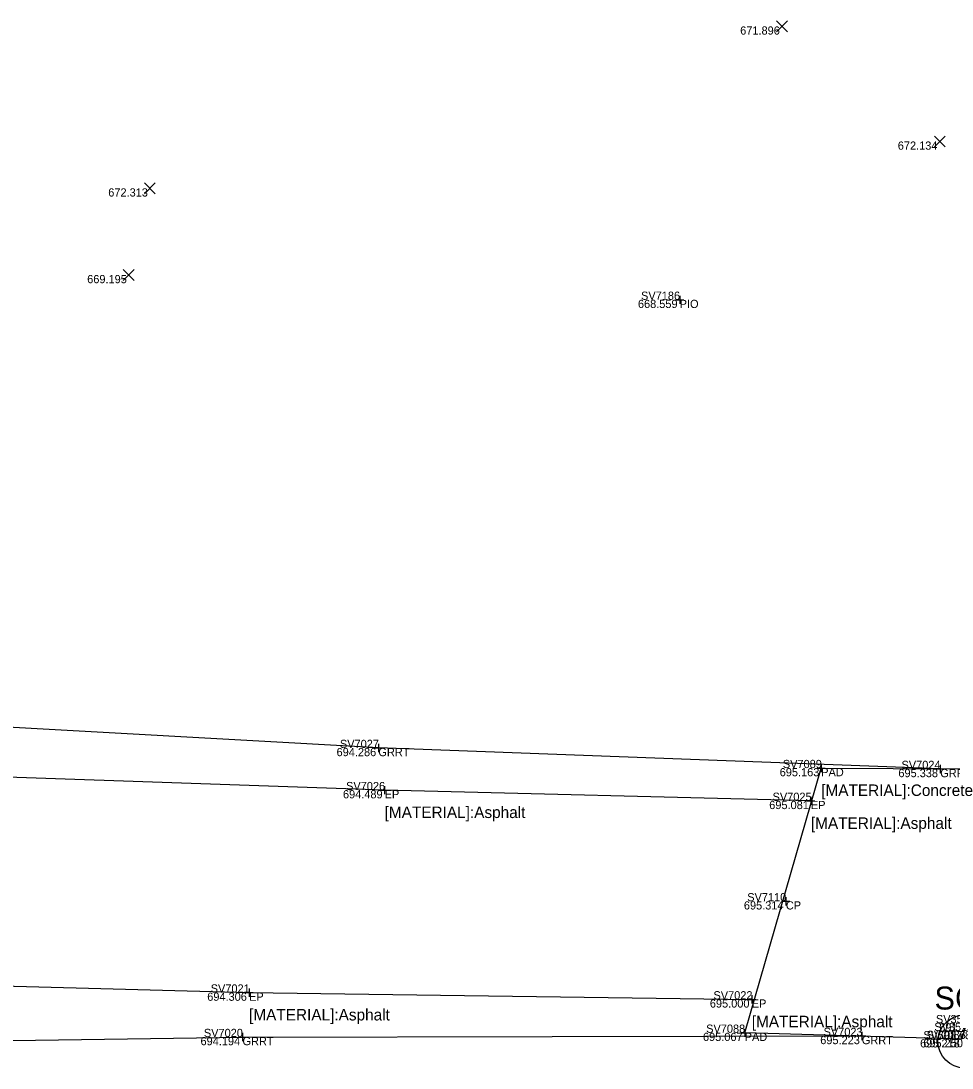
# Model space of a CAD drawing. Extents: x 1660019 to 1662995, y 619975 to 620342.
# Drawn here: x 1661112.6 to 1661226.1, y 620214.3 to 620342 of the extents above; entities that cross this region are included whole.
import ezdxf

# ---------------------------------------------------------------- set-up
doc = ezdxf.new("R2010")
doc.units = 0
for name, color, linetype in [('BR_X_Rail_Object', 7, 'Continuous'), ('BR_X_SV_Bottom_of_Beam_Text', 7, 'Continuous'), ('BR_X_SV_Deck_Top_Text', 7, 'Continuous'), ('DR_X_Elev_Flow', 7, 'Continuous'), ('PV_X_EOP', 7, 'Continuous'), ('RD_P_GR_Lt', 7, 'Continuous'), ('RD_P_GR_Rt', 7, 'Continuous'), ('RD_X_Concrete_Pad', 7, 'Continuous'), ('RD_X_GR_Bar', 7, 'Continuous'), ('RD_X_GR_Rt', 7, 'Continuous'), ('RD_X_Text', 7, 'Continuous'), ('RD_X_Wall', 7, 'Continuous'), ('SC_Scratch6', 7, 'Continuous'), ('SV_X_Text', 7, 'Continuous')]:
    doc.layers.add(name, color=color, linetype=linetype)

msp = doc.modelspace()

# ---------------------------------------------------------------- linework, layer by layer
at = {"layer": 'DR_X_Elev_Flow'}
for p, q in [((1661192.42, 620307.99), (1661193.42, 620307.99)), ((1661192.92, 620308.49), (1661192.92, 620307.49)), ((1661192.92, 620307.99), (1661192.92, 620307.99))]:
    msp.add_line(p, q, dxfattribs=at)
at = {"layer": 'PV_X_EOP'}
for points in [[(1661208.92, 620246.9), (1661156.94, 620248.21), (1661087.29, 620250.6), (1661037.39, 620250.48), (1660981.01, 620252.16), (1660916.41, 620253.34), (1660855.2, 620254.44), (1660801.44, 620255.57), (1660749.64, 620256.49), (1660700.03, 620257.78), (1660643.44, 620258.64), (1660593.17, 620259.57)], [(1660597.37, 620234.1), (1660651.64, 620233.44), (1660703.42, 620232.61), (1660757.32, 620231.35), (1660809.76, 620230.12), (1660857.03, 620229.26), (1660910.07, 620228.44), (1660968.25, 620227.38), (1661028.27, 620226.15), (1661081.58, 620225.11), (1661140.41, 620223.53), (1661201.71, 620222.7)]]:
    msp.add_lwpolyline(points, dxfattribs=at)
at = {"layer": 'RD_P_GR_Lt'}
for p, q in [((1661155.68, 620253.35), (1661156.68, 620253.35)), ((1661156.18, 620253.85), (1661156.18, 620252.85)), ((1661156.18, 620253.35), (1661156.18, 620253.35)), ((1661209.68, 620250.9), (1661210.68, 620250.9)), ((1661210.18, 620251.4), (1661210.18, 620250.4)), ((1661210.18, 620250.9), (1661210.18, 620250.9)), ((1661224.19, 620250.79), (1661225.19, 620250.79)), ((1661224.69, 620251.29), (1661224.69, 620250.29)), ((1661224.69, 620250.79), (1661224.69, 620250.79)), ((1661156.44, 620248.21), (1661157.44, 620248.21)), ((1661156.94, 620248.71), (1661156.94, 620247.71)), ((1661156.94, 620248.21), (1661156.94, 620248.21)), ((1661208.42, 620246.9), (1661209.42, 620246.9)), ((1661208.92, 620247.4), (1661208.92, 620246.4)), ((1661208.92, 620246.9), (1661208.92, 620246.9)), ((1661205.87, 620235.16), (1661205.87, 620234.16)), ((1661205.37, 620234.66), (1661206.37, 620234.66)), ((1661205.87, 620234.66), (1661205.87, 620234.66)), ((1661140.41, 620224.03), (1661140.41, 620223.03)), ((1661139.91, 620223.53), (1661140.91, 620223.53)), ((1661140.41, 620223.53), (1661140.41, 620223.53)), ((1661201.21, 620222.7), (1661202.21, 620222.7)), ((1661201.71, 620223.2), (1661201.71, 620222.2)), ((1661201.71, 620222.7), (1661201.71, 620222.7)), ((1661139.61, 620218.61), (1661139.61, 620217.61)), ((1661200.35, 620218.63), (1661201.35, 620218.63)), ((1661200.85, 620219.13), (1661200.85, 620218.13)), ((1661200.85, 620218.63), (1661200.85, 620218.63)), ((1661215.13, 620218.74), (1661215.13, 620217.74)), ((1661139.11, 620218.11), (1661140.11, 620218.11)), ((1661139.61, 620218.11), (1661139.61, 620218.11)), ((1661214.63, 620218.24), (1661215.63, 620218.24)), ((1661215.13, 620218.24), (1661215.13, 620218.24))]:
    msp.add_line(p, q, dxfattribs=at)
at = {"layer": 'RD_P_GR_Rt'}
for p, q in [((1661204.73, 620340.65), (1661206.07, 620341.99)), ((1661204.73, 620341.99), (1661206.07, 620340.65)), ((1661223.98, 620326.62), (1661225.31, 620327.95)), ((1661223.98, 620327.95), (1661225.31, 620326.62)), ((1661127.64, 620320.91), (1661128.97, 620322.25)), ((1661127.64, 620322.25), (1661128.97, 620320.91)), ((1661125.07, 620310.34), (1661126.4, 620311.68)), ((1661125.07, 620311.68), (1661126.4, 620310.34))]:
    msp.add_line(p, q, dxfattribs=at)
at = {"layer": 'RD_X_Concrete_Pad'}
msp.add_lwpolyline([(1661227.34, 620217.84), (1661200.85, 620218.63), (1661210.18, 620250.9), (1661236.48, 620250.77)], close=True, dxfattribs=at)
at = {"layer": 'RD_X_GR_Rt'}
for points in [[(1661224.69, 620250.79), (1661156.18, 620253.35), (1661087.54, 620257.19), (1661037.26, 620258.5), (1660981.37, 620259.47), (1660918.68, 620260.81), (1660856.77, 620262.08), (1660800.7, 620262.74), (1660750.31, 620264.54), (1660700.27, 620265.16), (1660644.43, 620266.52), (1660592.86, 620267.53)], [(1660596.86, 620226.32), (1660650.68, 620225.81), (1660702.7, 620224.83), (1660759.05, 620223.97), (1660808.86, 620222.78), (1660856.77, 620221.69), (1660908.98, 620220.55), (1660971.26, 620219.59), (1661027.54, 620217.92), (1661083.51, 620217.29), (1661139.61, 620218.11), (1661215.13, 620218.24)]]:
    msp.add_lwpolyline(points, dxfattribs=at)
at = {"layer": 'SC_Scratch6'}
msp.add_circle((1661227.66, 620217.57), 3.24, dxfattribs=at)

# ---------------------------------------------------------------- texts
at = {"layer": 'BR_X_Rail_Object'}
for s, p in [('PIO', (1661192.92, 620306.99)), ('GRRT', (1661156.18, 620252.35)), ('PAD', (1661210.18, 620249.9)), ('GRRT', (1661224.69, 620249.79)), ('EP', (1661156.94, 620247.21)), ('EP', (1661208.92, 620245.9)), ('CP', (1661205.87, 620233.66)), ('EP', (1661140.41, 620222.53)), ('EP', (1661201.71, 620221.7)), ('PAD', (1661200.85, 620217.63)), ('GRRT', (1661139.61, 620217.11)), ('GRRT', (1661215.13, 620217.24))]:
    msp.add_text(s, height=1, dxfattribs=at).set_placement(p)
at = {"layer": 'BR_X_SV_Bottom_of_Beam_Text'}
for s, p in [('SV35157', (1661223.97, 620218.85)), ('SV35156', (1661224.17, 620219.8)), ('691.796', (1661224.57, 620218.8)), ('691.788', (1661224.36, 620217.85))]:
    msp.add_text(s, height=1, dxfattribs=at).set_placement(p)
at = {"layer": 'BR_X_SV_Deck_Top_Text'}
for s, p in [('SV7086', (1661223.04, 620217.87)), ('695.250', (1661222.63, 620216.87))]:
    msp.add_text(s, height=1, dxfattribs=at).set_placement(p)
at = {"layer": 'RD_X_GR_Bar'}
for s, p in [('671.896', (1661200.3, 620340.32)), ('672.134', (1661219.52, 620326.29)), ('672.313', (1661123.24, 620320.58)), ('669.195', (1661120.67, 620310.01)), ('668.559', (1661187.83, 620306.99)), ('694.286', (1661151.08, 620252.35)), ('695.163', (1661205.12, 620249.9)), ('695.338', (1661219.59, 620249.79)), ('694.489', (1661151.86, 620247.21)), ('695.081', (1661203.84, 620245.9)), ('695.314', (1661200.75, 620233.66)), ('694.306', (1661135.31, 620222.53)), ('695.000', (1661196.6, 620221.7)), ('695.067', (1661195.76, 620217.63)), ('694.194', (1661134.49, 620217.11)), ('695.223', (1661210.06, 620217.24)), ('695.218', (1661222.24, 620216.84))]:
    msp.add_text(s, height=1, dxfattribs=at).set_placement(p)
at = {"layer": 'RD_X_Text'}
msp.add_text('SCUPPER', height=2.8, dxfattribs=at).set_placement((1661223.99, 620221.46))
at = {"layer": 'RD_X_Wall'}
for s, p in [('SV7186', (1661188.21, 620307.99)), ('SV7027', (1661151.49, 620253.35)), ('SV7089', (1661205.5, 620250.9)), ('SV7024', (1661219.97, 620250.79)), ('SV7026', (1661152.24, 620248.21)), ('SV7025', (1661204.25, 620246.9)), ('SV7110', (1661201.16, 620234.66)), ('SV7021', (1661135.73, 620223.53)), ('SV7022', (1661197.04, 620222.7)), ('SV7020', (1661134.9, 620218.11)), ('SV7088', (1661196.15, 620218.63)), ('SV7023', (1661210.47, 620218.24)), ('SV7087', (1661222.64, 620217.84))]:
    msp.add_text(s, height=1, dxfattribs=at).set_placement(p)
at = {"layer": 'SV_X_Text'}
for s, p in [('[MATERIAL]:Concrete', (1661210.18, 620247.5)), ('[MATERIAL]:Asphalt', (1661156.94, 620244.81)), ('[MATERIAL]:Asphalt', (1661208.92, 620243.49)), ('[MATERIAL]:Asphalt', (1661140.41, 620220.13)), ('[MATERIAL]:Asphalt', (1661201.71, 620219.3))]:
    msp.add_text(s, height=1.4, dxfattribs=at).set_placement(p)

doc.saveas('drawing.dxf')
